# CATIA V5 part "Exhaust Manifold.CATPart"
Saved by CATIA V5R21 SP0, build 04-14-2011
Part number: Part1
Bounding box of the stored display mesh (mm): x 0 to 252.882, y -53.016 to 413.016, z -175 to 64.22
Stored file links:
  G:\CATIA\Exhaust Manifold.CATPart
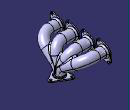
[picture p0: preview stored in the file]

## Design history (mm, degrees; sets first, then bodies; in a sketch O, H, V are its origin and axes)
Body1 (main body)
  Sketch1 on yz-plane, origin (0, 0, 0), H (0, 1, 0), V (0, 0, 1)
    circle A1 centre (0, 0) radius 34
    construction line L1 (0, 0) -> (-40.018, 51.2207)
    point P1 (-40.018, 51.2207)
    axis line L2 (40.018, -51.2207) -> (0, 0)
    point P2 (40.018, -51.2207)
    circle A2 centre (-40.018, 51.2207) radius 8
    circle A3 centre (40.018, -51.2207) radius 8
    point P3 (39, 0)
    arc A4 centre (0, 0) radius 50 from (49.9169, 2.8812) to (14.8716, 47.7372) ccw
    arc A5 centre (40.018, -51.2207) radius 13 from (36.1514, -63.6324) to (52.9964, -50.4716) ccw
    arc A6 centre (-40.018, 51.2207) radius 13 from (-36.1514, 63.6324) to (-52.9964, 50.4716) ccw
    line L3 (-36.1514, 63.6324) -> (14.8716, 47.7372)
    line L4 (52.9964, -50.4716) -> (49.9169, 2.8812)
    line L5 (-52.9964, 50.4716) -> (-49.9169, -2.8812)
    point P9 (-49.9169, -2.8812)
    line L6 (-14.8716, -47.7372) -> (36.1514, -63.6324)
    arc A7 centre (0, 0) radius 50 from (-49.9169, -2.8812) to (-14.8716, -47.7372) ccw
    radius A1 = 34
    radius A2 = 8
    radius A3 = 8
    angle V L1 = 38
    radius A4 = 50
    radius A6 = 13
    radius A5 = 13
    distance P2 O = 65
    distance P1 O = 65
    coincidence: P2 L1, P3 H, A4 P9, A4 A7
    parallelism: L2 L1
    tangency: L3 A6, L3 A4, L4 A5, L4 A4, L5 A6, L5 A4, L6 A4, L6 A5
  Pad1: profile Sketch1, direction (1, 0, 0), length 8
  RectPattern1: of Pad1, direction 1 instances 4, spacing 120, along yz-plane
  Plane1: type Offset, RefPlane xy-plane, Offset 175, reversed
  Sketch2 on Plane1, origin (0, 0, -175), H (0, -1, 0), V (1, 0, 0)
    construction line L1 (-179.9892, 8) -> (-179.9892, 168)
    construction circle A1 centre (-179.9892, 168) radius 35.1088
    circle A2 centre (-179.9892, 237.8912) radius 8
    point P3 (-179.9892, 237.8912)
    circle A3 centre (-118.9892, 132.8912) radius 8
    point P4 (-118.9892, 132.8912)
    circle A4 centre (-240.9892, 132.8912) radius 8
    point P5 (-240.9892, 132.8912)
    construction line L2 (-118.9892, 132.8912) -> (-179.9892, 237.8912)
    construction line L3 (-240.9892, 132.8912) -> (-179.9892, 237.8912)
    axis line L4 (-240.9892, 132.8912) -> (-118.9892, 132.8912)
    circle A5 centre (-179.9892, 168) radius 34
    arc A6 centre (-179.9892, 237.8912) radius 15 from (-167.0191, 245.4263) to (-192.9593, 245.4263) ccw
    arc A7 centre (-118.9892, 132.8912) radius 15 from (-118.9892, 117.8912) to (-106.0191, 140.4263) ccw
    arc A8 centre (-240.9892, 132.8912) radius 15 from (-253.9593, 140.4263) to (-240.9892, 117.8912) ccw
    line L5 (-106.0191, 140.4263) -> (-167.0191, 245.4263)
    line L6 (-192.9593, 245.4263) -> (-253.9593, 140.4263)
    line L7 (-240.9892, 117.8912) -> (-118.9892, 117.8912)
    length L1 = 160
    radius A2 = 8
    radius A3 = 8
    radius A4 = 8
    distance P3 L4 = 105
    distance P4 P5 = 122
    radius A5 = 34
    radius A6 = 15
    radius A7 = 15
    radius A8 = 15
    vertical: L1 V
    coincidence: P3 L1
    horizontal: L4 H
    tangency: A1 L2, A1 L4, A1 L3, L5 A7, L5 A6, L6 A6, L6 A8, L7 A8, L7 A7
  Pad2: profile Sketch2, direction (0, 0, 1), length 8
  Point1: type Center, Curve edge [face of RectPattern1 | face of RectPattern1]
  Point2: type Center, Curve edge [end face of Pad2 | face of Pad2 from Sketch2.A5]
  Line1: type PtDir, RefPoint Point1, Direction (1, 0, 0), Start 0, End 139.5
  Line2: type PtDir, RefPoint Point2, Direction (0, 0, 1), Start 0, End 50
  Line3: type PtPt, FirstPoint vertex of Line1, SecondPoint vertex of Line2
  Corner1: Element1 Line3, Element2 Line1, Radius 90
  Corner2: Element1 Corner1, Element2 Line2, Radius 70
  Sweep1: type Circle, Guide Corner2, Radius 35
  Point3: type Center, Curve edge [face of RectPattern1 | face of RectPattern1]
  Line4: type PtDir, RefPoint Point3, Direction (1, 0, 0), Start 0, End 139.5
  Line5: type PtDir, RefPoint Point2, Direction (0, 0, 1), Start 0, End 40
  Line6: type PtPt, FirstPoint vertex of Line4, SecondPoint vertex of Line5
  Corner3: Element1 Line4, Element2 Line6, Radius 70
  Corner4: Element1 Corner3, Element2 Line5, Radius 30
  Sweep2: type Circle, Guide Corner4, Radius 35
  Plane2: type OffsetPt, RefPlane zx-plane, RefPoint Point2
  MultiSel1
  CloseSurface1: CloseElement {symmetry ToTransfor Sweep2, Reference Plane2}
  CloseSurface2: CloseElement {symmetry ToTransfor Sweep1, Reference Plane2}
  CloseSurface3: CloseElement Sweep2
  CloseSurface4: CloseElement Sweep1
  Shell1: ExtOffset 0, Face (face of CloseSurface1; face of CloseSurface3; face of CloseSurface4; face of CloseSurface2; face of CloseSurface4), IntOffset 3
  Fillet1: radius 10, on edge [face of CloseSurface2 | end face of Pad1]; edge [face of CloseSurface1 | face of RectPattern1]; edge [face of RectPattern1 | face of CloseSurface3]; edge [face of RectPattern1 | face of CloseSurface4]
  Fillet2: radius 10, on edge [face of CloseSurface4 | face of CloseSurface3]; edge [face of CloseSurface3 | face of CloseSurface1]; edge [face of CloseSurface1 | face of CloseSurface2]
  Fillet3: radius 5, on edge [face of CloseSurface4 | end face of Pad2]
